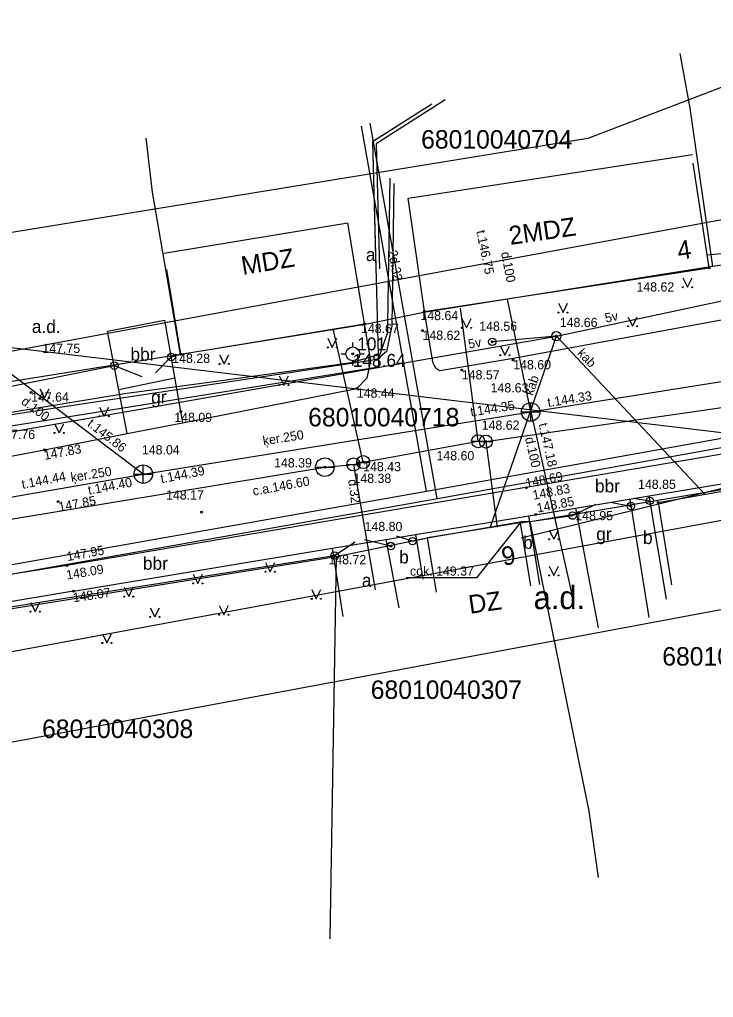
# Model space of a CAD drawing. Extents: x 728492 to 729038, y 272968 to 273171.
# Drawn here: x 728588.9 to 728626.4, y 273032.9 to 273085.8 of the extents above; entities that cross this region are included whole.
import ezdxf

# ---------------------------------------------------------------- set-up
doc = ezdxf.new("R2010")
doc.units = 0
for name, color, linetype in [('APGR_SARK_####_####_#', 7, 'Continuous'), ('BUVE_BDET_####_####_#', 7, 'Continuous'), ('BUVE_BDET_####_TKST_#', 7, 'Continuous'), ('BUVE_EKAS_####_####_#', 7, 'Continuous'), ('BUVE_EKAS_ADRS_TKST_#', 7, 'Continuous'), ('BUVE_EKAS_RAKS_TKST_#', 7, 'Continuous'), ('CELI_CAPM_####_####_#', 7, 'Continuous'), ('CELI_CMAL_####_####_#', 7, 'Continuous'), ('CELI_CSEG_####_TKST_#', 7, 'Continuous'), ('CELI_SEGL_####_####_#', 7, 'Continuous'), ('ELEK_ELEM_####_####_#', 7, 'Continuous'), ('ELEK_STUT_####_####_#', 7, 'Continuous'), ('ELEK_VADP_VSPR_####_#', 7, 'Continuous'), ('ELEK_VADP_ZSPR_####_#', 7, 'Continuous'), ('ELEK_VADV_ZSPR_####_#', 7, 'Continuous'), ('ELEK_VADV_ZSPR_TKST_#', 7, 'Continuous'), ('GEOD_ELEM_####_####_#', 7, 'Continuous'), ('GEOD_ELEM_####_TKST_#', 7, 'Continuous'), ('Level 62', 7, 'Continuous'), ('NORB_ELEM_####_####_#', 7, 'Continuous'), ('NORB_ZOGS_BARJ_####_#', 7, 'Continuous'), ('NORB_ZOGS_KOKA_####_#', 7, 'Continuous'), ('NORB_ZOGS_ZSTP_####_#', 7, 'Continuous'), ('RAMI_UZMR_####_####_#', 7, 'Continuous'), ('RELJ_AATZ_####_TKST_#', 7, 'Continuous'), ('RELJ_ELEM_####_####_#', 7, 'Continuous'), ('ROBZ_KADS_####_TKST_#', 7, 'Continuous'), ('ROBZ_UZMR_####_####_#', 7, 'Continuous'), ('SAKT_VADV_KLIN_####_#', 7, 'Continuous'), ('SILT_VADP_UDEN_####_#', 7, 'Continuous'), ('SILT_VADP_UDEN_TKST_#', 7, 'Continuous'), ('SKAN_ELEM_####_####_#', 7, 'Continuous'), ('SKAN_VADP_PAST_####_#', 7, 'Continuous'), ('SKAN_VADP_PAST_TKST_#', 7, 'Continuous'), ('TERT_ELEM_####_####_#', 7, 'Continuous'), ('TERT_IZMT_####_TKST_#', 7, 'Continuous'), ('UDTK_ELEM_####_####_#', 7, 'Continuous'), ('UDTK_ELEM_####_TKST_#', 7, 'Continuous'), ('UDTK_VADP_UDEN_####_#', 7, 'Continuous'), ('UDTK_VADP_UDEN_TKST_#', 7, 'Continuous')]:
    doc.layers.add(name, color=color, linetype=linetype)

msp = doc.modelspace()

# ---------------------------------------------------------------- linework, layer by layer
at = {"layer": 'APGR_SARK_####_####_#'}
for points in [[(728659.143, 273080.982), (728541.407, 273059.185)], [(728661.295, 273065.109), (728551.197, 273044.726)]]:
    msp.add_lwpolyline(points, dxfattribs=at)
at = {"layer": 'BUVE_BDET_####_####_#'}
msp.add_lwpolyline([(728615.971, 273058.601), (728613.605, 273055.621), (728609.798, 273055.621)], dxfattribs=at)
at = {"layer": 'BUVE_EKAS_####_####_#'}
for p, q in [((728609.897, 273076.179), (728625.296, 273078.536)), ((728626.186, 273072.407), (728625.319, 273078.071)), ((728610.787, 273070.05), (728609.897, 273076.179)), ((728596.708, 273073.202), (728606.645, 273074.845)), ((728607.549, 273069.376), (728606.645, 273074.845)), ((728597.612, 273067.733), (728596.855, 273072.309)), ((728610.787, 273070.05), (728626.186, 273072.407)), ((728597.612, 273067.733), (728607.549, 273069.376)), ((728623.429, 273059.709), (728632.791, 273061.372)), ((728623.429, 273059.709), (728624.16, 273055.247)), ((728615.971, 273058.601), (728610.946, 273057.793)), ((728615.971, 273058.601), (728616.519, 273055.191)), ((728611.429, 273054.849), (728610.946, 273057.793))]:
    msp.add_line(p, q, dxfattribs=at)
at = {"layer": 'CELI_CAPM_####_####_#'}
msp.add_line((728630.786, 273062.984), (728591.431, 273056.294), dxfattribs=at)
msp.add_lwpolyline([(728591.431, 273056.294), (728577.849, 273054.135), (728577.526, 273054.029), (728577.203, 273053.778), (728577.017, 273053.345), (728577.072, 273052.432)], dxfattribs=at)
at = {"layer": 'CELI_CMAL_####_####_#'}
for p, q in [((728611.241, 273067.302), (728610.787, 273070.05)), ((728615.604, 273067.516), (728631.326, 273070.412)), ((728607.884, 273067.35), (728607.549, 273069.376)), ((728611.627, 273066.852), (728615.604, 273067.516)), ((728597.702, 273064.026), (728607.125, 273065.877)), ((728590.22, 273062.556), (728594.693, 273063.435)), ((728622.936, 273060.066), (728641.923, 273063.209)), ((728588.309, 273062.194), (728590.22, 273062.556)), ((728590.22, 273062.556), (728590.22, 273062.556)), ((728623.877, 273054.483), (728622.936, 273060.066)), ((728610.303, 273057.974), (728618.954, 273059.406)), ((728618.954, 273059.406), (728620.178, 273052.925)), ((728616.415, 273058.986), (728617.013, 273055.27)), ((728610.303, 273057.974), (728610.692, 273055.554)), ((728591.788, 273054.908), (728605.801, 273057.228)), ((728605.801, 273057.228), (728606.37, 273053.532)), ((728608.701, 273057.708), (728608.701, 273057.708))]:
    msp.add_line(p, q, dxfattribs=at)
for points in [[(728594.693, 273063.435), (728593.642, 273068.981), (728596.728, 273069.566), (728597.702, 273064.026)], [(728607.125, 273065.877), (728607.688, 273066.453), (728607.884, 273067.35)], [(728591.788, 273054.908), (728577.072, 273052.432)]]:
    msp.add_lwpolyline(points, dxfattribs=at)
msp.add_arc((728611.826, 273067.413), 0.595, 190.7196, 250.457, dxfattribs=at)
at = {"layer": 'CELI_SEGL_####_####_#'}
for p, q in [((728594.693, 273063.435), (728597.702, 273064.026)), ((728618.954, 273059.406), (728622.936, 273060.066)), ((728621.895, 273059.893), (728622.932, 273053.483)), ((728608.701, 273057.708), (728610.303, 273057.974)), ((728605.801, 273057.228), (728608.701, 273057.708)), ((728608.701, 273057.708), (728609.398, 273053.999))]:
    msp.add_line(p, q, dxfattribs=at)
msp.add_lwpolyline([(728594.241, 273065.818), (728597.276, 273066.448)], dxfattribs=at)
at = {"layer": 'ELEK_ELEM_####_####_#'}
for centre, radius in [((728617.923, 273068.708), 0.25), ((728614.457, 273068.405), 0.2)]:
    msp.add_circle(centre, radius, dxfattribs=at)
at = {"layer": 'ELEK_STUT_####_####_#'}
msp.add_line((728617.923, 273068.708), (728614.457, 273068.405), dxfattribs=at)
at = {"layer": 'ELEK_VADP_VSPR_####_#'}
for points in [[(728611.184, 273081.264), (728607.971, 273079.223), (728608.156, 273072.311)], [(728609.286, 273080.058), (728607.971, 273079.223), (728608.297, 273067.03), (728567.061, 273060.412)]]:
    msp.add_lwpolyline(points, dxfattribs=at)
at = {"layer": 'ELEK_VADP_ZSPR_####_#'}
for points in [[(728611.913, 273081.49), (728608.174, 273079.115), (728608.355, 273072.352)], [(728537.081, 273033.933), (728536.029, 273037.608), (728532.423, 273051.927), (728532.247, 273053.87), (728532.195, 273055.313), (728532.733, 273055.949), (728533.306, 273056.402), (728544.74, 273057.861), (728548.075, 273058.286), (728556.859, 273059.593), (728568.226, 273061.284), (728585.454, 273064.109), (728594.552, 273065.598), (728599.536, 273066.281), (728606.829, 273067.282), (728608.394, 273067.733), (728608.806, 273068.923), (728608.813, 273069.373), (728608.935, 273077.264)], [(728609.132, 273076.972), (728609.028, 273069.268), (728608.736, 273067.883), (728608.238, 273067.455), (728607.796, 273067.368), (728594.151, 273065.314), (728588.415, 273064.454), (728582.59, 273063.515), (728568.697, 273061.216), (728567.895, 273060.73), (728567.578, 273060.071)]]:
    msp.add_lwpolyline(points, dxfattribs=at)
at = {"layer": 'ELEK_VADV_ZSPR_####_#'}
for p, q in [((728617.923, 273068.708), (728666.081, 273078.979)), ((728577.706, 273061.659), (728617.923, 273068.708)), ((728614.336, 273058.338), (728617.923, 273068.708)), ((728617.923, 273068.708), (728625.963, 273060.159))]:
    msp.add_line(p, q, dxfattribs=at)
at = {"layer": 'GEOD_ELEM_####_####_#'}
for p, q in [((728606.906, 273068.123), (728606.906, 273068.373)), ((728606.281, 273067.748), (728606.531, 273067.748)), ((728606.906, 273067.123), (728606.906, 273067.373)), ((728607.281, 273067.748), (728607.531, 273067.748))]:
    msp.add_line(p, q, dxfattribs=at)
for radius in [0.375, 0.05]:
    msp.add_circle((728606.906, 273067.748), radius, dxfattribs=at)
at = {"layer": 'NORB_ELEM_####_####_#'}
for centre in [(728594.005, 273067.114), (728597.087, 273067.582), (728622.982, 273059.794), (728621.956, 273059.514), (728618.801, 273058.999), (728610.139, 273057.615), (728608.966, 273057.347), (728605.924, 273056.836)]:
    msp.add_circle(centre, 0.202, dxfattribs=at)
at = {"layer": 'NORB_ZOGS_BARJ_####_#'}
for points in [[(728596.239, 273066.725), (728597.087, 273067.582)], [(728594.005, 273067.114), (728595.485, 273066.533)], [(728622.105, 273059.935), (728622.982, 273059.794)], [(728618.801, 273058.999), (728620.053, 273059.625)], [(728620.855, 273059.716), (728621.956, 273059.514)], [(728610.138, 273057.615), (728609.269, 273057.889)], [(728605.924, 273056.836), (728607.039, 273057.586)], [(728608.966, 273057.347), (728607.542, 273057.687)]]:
    msp.add_lwpolyline(points, dxfattribs=at)
at = {"layer": 'NORB_ZOGS_KOKA_####_#'}
msp.add_lwpolyline([(728626.077, 273073.117), (728630.292, 273073.503)], dxfattribs=at)
at = {"layer": 'NORB_ZOGS_ZSTP_####_#'}
for points in [[(728597.087, 273067.582), (728597.612, 273067.733)], [(728587.68, 273065.855), (728594.005, 273067.114)], [(728615.971, 273058.601), (728618.801, 273058.999)], [(728610.139, 273057.615), (728610.946, 273057.793)], [(728584.143, 273053.398), (728605.924, 273056.836)]]:
    msp.add_lwpolyline(points, dxfattribs=at)
at = {"layer": 'RAMI_UZMR_####_####_#'}
for points in [[(728726.814, 273102.175), (728686.914, 273096.216), (728659.323, 273094.615), (728619.629, 273079.414), (728545.121, 273067.256)], [(728545.121, 273067.256), (728525.538, 273066.106), (728511.145, 273059.016), (728527.731, 273033.328), (728550.271, 273033.197), (728572.013, 273034.886), (728580.562, 273045.27), (728653.673, 273058.931), (728671.713, 273053.291), (728688.721, 273058.407), (728702.149, 273066.922)]]:
    msp.add_lwpolyline(points, dxfattribs=at)
at = {"layer": 'RELJ_ELEM_####_####_#'}
for centre in [(728626.186, 273072.407), (728610.787, 273070.05), (728607.549, 273069.376), (728610.681, 273069.009), (728607.729, 273068.302), (728614.457, 273068.405), (728617.923, 273068.708), (728606.906, 273067.748), (728597.612, 273067.733), (728615.59, 273067.417), (728594.005, 273067.114), (728612.809, 273066.868), (728589.501, 273065.663), (728607.125, 273065.877), (728597.612, 273064.627), (728616.534, 273064.605), (728614.11, 273063.005), (728590.22, 273062.556), (728605.396, 273061.619), (728607.469, 273061.897), (728595.572, 273061.244), (728616.299, 273060.508), (728590.963, 273059.755), (728621.956, 273059.514), (728623.429, 273059.709), (728598.719, 273059.188), (728616.814, 273059.063), (728608.966, 273057.347), (728605.924, 273056.836), (728591.431, 273056.294), (728591.788, 273054.908)]:
    msp.add_circle(centre, 0.05, dxfattribs=at)
at = {"layer": 'ROBZ_UZMR_####_####_#'}
for p, q in [((728624.61, 273084.002), (728625.148, 273081.05)), ((728625.148, 273081.05), (728626.365, 273072.477)), ((728596.07, 273076.503), (728595.736, 273079.424)), ((728597.584, 273067.721), (728596.07, 273076.503)), ((728630.305, 273073.064), (728626.365, 273072.477)), ((728626.365, 273072.477), (728610.761, 273069.994)), ((728610.761, 273069.994), (728607.569, 273069.334)), ((728607.569, 273069.334), (728597.584, 273067.721)), ((728597.584, 273067.721), (728547.311, 273059.662)), ((728616.498, 273058.682), (728633.894, 273061.592)), ((728610.841, 273057.776), (728616.062, 273058.672)), ((728616.062, 273058.672), (728616.498, 273058.682)), ((728619.697, 273042.998), (728616.498, 273058.682)), ((728606.005, 273056.779), (728610.841, 273057.776)), ((728578.327, 273052.35), (728606.005, 273056.779)), ((728606.005, 273056.779), (728605.672, 273036.097)), ((728620.2, 273039.418), (728619.697, 273042.998))]:
    msp.add_line(p, q, dxfattribs=at)
at = {"layer": 'SAKT_VADV_KLIN_####_#'}
msp.add_line((728578.857, 273069.237), (728635.134, 273062.502), dxfattribs=at)
msp.add_lwpolyline([(728635.134, 273062.502), (728616.023, 273057.783)], dxfattribs=at)
at = {"layer": 'SILT_VADP_UDEN_####_#'}
for p, q in [((728610.89, 273060.328), (728607.371, 273080.08)), ((728611.47, 273059.924), (728607.852, 273080.229))]:
    msp.add_line(p, q, dxfattribs=at)
for points in [[(728554.662, 273032.952), (728554.113, 273035.473), (728554.267, 273035.774), (728581.419, 273054.878), (728582.018, 273055.208), (728610.89, 273060.328), (728630.183, 273063.782), (728638.039, 273065.289), (728652.893, 273068.386), (728653.925, 273076.859), (728654.802, 273077.089)], [(728555.193, 273032.922), (728554.64, 273035.405), (728554.656, 273035.436), (728581.684, 273054.453), (728582.187, 273054.73), (728610.978, 273059.835), (728630.274, 273063.29), (728638.144, 273064.8), (728653.493, 273067.873), (728654.384, 273076.462), (728654.897, 273076.597)]]:
    msp.add_lwpolyline(points, dxfattribs=at)
at = {"layer": 'SKAN_ELEM_####_####_#'}
for p, q in [((728616.534, 273064.105), (728616.534, 273065.105)), ((728616.034, 273064.605), (728617.034, 273064.605)), ((728595.572, 273060.744), (728595.572, 273061.744)), ((728595.072, 273061.244), (728596.072, 273061.244))]:
    msp.add_line(p, q, dxfattribs=at)
for centre in [(728616.534, 273064.605), (728595.572, 273061.244)]:
    msp.add_circle(centre, 0.5, dxfattribs=at)
at = {"layer": 'SKAN_VADP_PAST_####_#'}
for points in [[(728616.534, 273064.605), (728669.124, 273072.987)], [(728616.534, 273064.605), (728615.275, 273070.702)], [(728565.936, 273055.685), (728588.276, 273059.976), (728595.572, 273061.244), (728588.275, 273066.761)], [(728595.572, 273061.244), (728616.534, 273064.605), (728618.819, 273054.491)]]:
    msp.add_lwpolyline(points, dxfattribs=at)
at = {"layer": 'TERT_ELEM_####_####_#'}
for p, q in [((728624.768, 273071.859), (728625.018, 273071.359)), ((728625.018, 273071.359), (728625.268, 273071.859)), ((728618.033, 273070.488), (728618.283, 273069.988)), ((728618.283, 273069.988), (728618.533, 273070.488)), ((728612.81, 273069.66), (728613.06, 273069.16)), ((728613.06, 273069.16), (728613.31, 273069.66)), ((728621.8, 273069.745), (728622.05, 273069.245)), ((728622.05, 273069.245), (728622.3, 273069.745)), ((728605.551, 273068.597), (728605.801, 273068.097)), ((728605.801, 273068.097), (728606.051, 273068.597)), ((728614.893, 273068.174), (728615.143, 273067.674)), ((728615.143, 273067.674), (728615.393, 273068.174)), ((728599.701, 273067.703), (728599.951, 273067.203)), ((728599.951, 273067.203), (728600.201, 273067.703)), ((728602.924, 273066.562), (728603.174, 273066.062)), ((728603.174, 273066.062), (728603.424, 273066.562)), ((728589.983, 273065.867), (728590.233, 273065.367)), ((728590.233, 273065.367), (728590.483, 273065.867)), ((728593.206, 273064.874), (728593.456, 273064.374)), ((728593.456, 273064.374), (728593.706, 273064.874)), ((728590.768, 273063.969), (728591.018, 273063.469)), ((728591.018, 273063.469), (728591.268, 273063.969)), ((728617.535, 273058.217), (728617.785, 273057.717)), ((728617.785, 273057.717), (728618.035, 273058.217)), ((728602.183, 273056.461), (728602.433, 273055.961)), ((728602.433, 273055.961), (728602.683, 273056.461)), ((728617.535, 273056.26), (728617.785, 273055.76)), ((728617.785, 273055.76), (728618.035, 273056.26)), ((728598.273, 273055.828), (728598.523, 273055.328)), ((728598.523, 273055.328), (728598.773, 273055.828)), ((728594.533, 273055.117), (728594.783, 273054.617)), ((728594.783, 273054.617), (728595.033, 273055.117)), ((728604.684, 273054.994), (728604.934, 273054.494)), ((728604.934, 273054.494), (728605.184, 273054.994)), ((728589.475, 273054.303), (728589.725, 273053.803)), ((728589.725, 273053.803), (728589.975, 273054.303)), ((728599.682, 273054.13), (728599.932, 273053.63)), ((728599.932, 273053.63), (728600.182, 273054.13)), ((728595.944, 273054.015), (728596.194, 273053.515)), ((728596.194, 273053.515), (728596.444, 273054.015)), ((728593.357, 273052.605), (728593.607, 273052.105)), ((728593.607, 273052.105), (728593.857, 273052.605))]:
    msp.add_line(p, q, dxfattribs=at)
for centre, radius in [((728624.768, 273071.359), 0.028), ((728625.268, 273071.359), 0.0263), ((728618.032, 273069.988), 0.028), ((728618.532, 273069.988), 0.0263), ((728612.81, 273069.159), 0.028), ((728613.31, 273069.159), 0.0263), ((728621.8, 273069.245), 0.028), ((728622.3, 273069.245), 0.0263), ((728605.551, 273068.096), 0.028), ((728606.051, 273068.096), 0.0263), ((728614.893, 273067.673), 0.028), ((728615.393, 273067.673), 0.0263), ((728599.701, 273067.203), 0.028), ((728600.201, 273067.203), 0.0263), ((728602.923, 273066.061), 0.028), ((728603.423, 273066.061), 0.0263), ((728589.983, 273065.366), 0.028), ((728590.483, 273065.366), 0.0263), ((728593.205, 273064.374), 0.028), ((728593.705, 273064.374), 0.0263), ((728590.768, 273063.469), 0.028), ((728591.268, 273063.469), 0.0263), ((728617.535, 273057.717), 0.028), ((728618.035, 273057.717), 0.0263), ((728602.183, 273055.961), 0.028), ((728602.683, 273055.961), 0.0263), ((728617.535, 273055.759), 0.028), ((728618.035, 273055.759), 0.0263), ((728598.273, 273055.328), 0.028), ((728598.773, 273055.328), 0.0263), ((728594.533, 273054.617), 0.028), ((728595.033, 273054.617), 0.0263), ((728604.684, 273054.493), 0.028), ((728605.184, 273054.493), 0.0263), ((728589.475, 273053.802), 0.028), ((728589.975, 273053.802), 0.0263), ((728595.944, 273053.515), 0.028), ((728596.444, 273053.515), 0.0263), ((728599.681, 273053.63), 0.028), ((728600.181, 273053.63), 0.0263), ((728593.356, 273052.104), 0.028), ((728593.856, 273052.104), 0.0263)]:
    msp.add_circle(centre, radius, dxfattribs=at)
at = {"layer": 'UDTK_ELEM_####_####_#'}
for p, q in [((728613.337, 273063.022), (728614.039, 273063.022)), ((728613.759, 273063.005), (728614.461, 273063.005)), ((728604.897, 273061.619), (728605.897, 273061.619)), ((728606.594, 273061.767), (728607.296, 273061.767)), ((728607.118, 273061.897), (728607.82, 273061.897))]:
    msp.add_line(p, q, dxfattribs=at)
for centre, radius in [((728613.688, 273063.022), 0.351), ((728614.11, 273063.005), 0.351), ((728605.397, 273061.619), 0.5), ((728606.945, 273061.767), 0.351), ((728607.469, 273061.897), 0.351)]:
    msp.add_circle(centre, radius, dxfattribs=at)
at = {"layer": 'UDTK_VADP_UDEN_####_#'}
for points in [[(728613.688, 273063.022), (728612.733, 273070.229)], [(728536.753, 273051.73), (728562.041, 273055.954), (728585.763, 273058.374), (728605.397, 273061.619), (728606.945, 273061.767), (728607.469, 273061.897), (728613.688, 273063.022), (728614.11, 273063.005), (728657.437, 273069.243)], [(728607.469, 273061.897), (728605.863, 273069.033)], [(728614.11, 273063.005), (728614.723, 273058.38)], [(728606.945, 273061.767), (728608.123, 273054.985)]]:
    msp.add_lwpolyline(points, dxfattribs=at)

# ---------------------------------------------------------------- texts
at = {"layer": 'BUVE_BDET_####_TKST_#'}
msp.add_text('cok. 149.37', height=0.49999, dxfattribs=at).set_placement((728610.003, 273055.747))
at = {"layer": 'BUVE_EKAS_ADRS_TKST_#'}
for s, rotation, p in [('4', 8.702, (728624.543, 273072.834)), ('9', 9.738, (728615.048, 273056.28))]:
    msp.add_text(s, height=1, rotation=rotation, dxfattribs=at).set_placement(p)
at = {"layer": 'BUVE_EKAS_RAKS_TKST_#'}
for s, rotation, p in [('2MDZ', 8.259, (728615.432, 273073.645)), ('MDZ', 9.388, (728600.958, 273072.016)), ('DZ', 8.101, (728613.246, 273053.681))]:
    msp.add_text(s, height=1, rotation=rotation, dxfattribs=at).set_placement(p)
at = {"layer": 'CELI_CSEG_####_TKST_#'}
for s, p in [('a', (728607.614, 273072.775)), ('bbr', (728594.878, 273067.378)), ('gr', (728595.996, 273065.066)), ('bbr', (728620.012, 273060.253)), ('b', (728616.123, 273057.193)), ('gr', (728620.081, 273057.657)), ('b', (728622.611, 273057.458)), ('bbr', (728595.55, 273056.065)), ('b', (728609.42, 273056.406)), ('a', (728607.397, 273055.146))]:
    msp.add_text(s, height=0.7, dxfattribs=at).set_placement(p)
at = {"layer": 'ELEK_VADV_ZSPR_TKST_#'}
for s, rotation, p in [('5v', 12.0395, (728620.608, 273069.434)), ('5v', 9.9415, (728613.199, 273068.032)), ('kab', 313.2425, (728619.026, 273067.754)), ('kab', 70.9194, (728616.642, 273065.464))]:
    msp.add_text(s, height=0.5, rotation=rotation, dxfattribs=at).set_placement(p)
at = {"layer": 'GEOD_ELEM_####_TKST_#'}
for s, p in [('101', (728607.147, 273067.938)), ('148.64', (728606.906, 273067.048))]:
    msp.add_text(s, height=0.7, dxfattribs=at).set_placement(p)
at = {"layer": 'Level 62'}
msp.add_text('a.d.', height=1.25, dxfattribs=at).set_placement((728616.692, 273053.936))
at = {"layer": 'RELJ_AATZ_####_TKST_#'}
for s, p in [(' 148.62', (728622.071, 273071.125)), (' 148.64', (728610.38, 273069.575)), (' 148.67', (728607.167, 273068.876)), (' 148.56', (728613.567, 273068.998)), (' 148.66', (728617.921, 273069.201)), ('148.62', (728610.681, 273068.509)), (' 147.75', (728589.927, 273067.796)), (' 148.28', (728596.952, 273067.258)), ('148.60', (728615.59, 273066.917)), ('148.57', (728612.809, 273066.368)), ('148.44', (728607.125, 273065.377)), ('147.64', (728589.501, 273065.163)), (' 148.09', (728597.065, 273064.062)), ('147.76', (728587.672, 273063.14)), (' 148.85', (728622.158, 273060.443)), (' 148.17', (728596.619, 273059.863)), (' 148.95', (728618.762, 273058.75)), (' 148.80', (728607.361, 273058.158)), (' 148.72', (728605.403, 273056.366))]:
    msp.add_text(s, height=0.5, dxfattribs=at).set_placement(p)
for s, rotation, p in [('147.83', 10.6625, (728590.241, 273062.007)), ('148.69', 11.319, (728616.305, 273060.498)), ('148.83', 10.9383, (728616.689, 273059.851)), ('147.85', 10.5336, (728591.034, 273059.211)), ('148.85', 10.9383, (728616.912, 273059.156)), ('147.95', 10.2697, (728591.479, 273056.532)), ('148.09', 9.5409, (728591.444, 273055.53)), ('148.07', 8.2992, (728591.805, 273054.307))]:
    msp.add_text(s, height=0.5, rotation=rotation, dxfattribs=at).set_placement(p)
at = {"layer": 'ROBZ_KADS_####_TKST_#'}
for s, p in [('68010040704', (728610.605, 273078.859)), ('68010040718', (728604.494, 273063.825)), ('68010040306', (728623.653, 273050.881)), ('68010040307', (728607.879, 273049.078)), ('68010040308', (728590.095, 273046.962))]:
    msp.add_text(s, height=1, dxfattribs=at).set_placement(p)
at = {"layer": 'SILT_VADP_UDEN_TKST_#'}
msp.add_text('2d.32', height=0.5, rotation=280.101, dxfattribs=at).set_placement((728608.821, 273073.32))
at = {"layer": 'SKAN_ELEM_####_####_#'}
for s, p in [('148.63', (728614.365, 273065.664)), ('148.04', (728595.497, 273062.308))]:
    msp.add_text(s, height=0.5, dxfattribs=at).set_placement(p)
at = {"layer": 'SKAN_VADP_PAST_TKST_#'}
for s, rotation, p in [('t.146.75', 281.669, (728613.586, 273074.385)), ('d.100', 280.97, (728614.926, 273073.223)), ('t.144.33', 9.141, (728617.486, 273064.871)), ('d.100', 322.907, (728588.923, 273065.087)), ('t.144.35', 9.141, (728613.312, 273064.356)), ('t.145.86', 322.073, (728592.505, 273063.882)), ('ķer.250', 9.109, (728602.081, 273062.793)), ('t.147.18', 282.782, (728616.952, 273063.948)), ('d.100', 282.782, (728616.225, 273063.191)), ('ķer.250', 9.109, (728591.687, 273060.813)), ('t.144.39', 10.873, (728596.554, 273060.747)), ('t.144.44', 10.873, (728589.041, 273060.442)), ('t.144.40', 10.873, (728592.628, 273060.12))]:
    msp.add_text(s, height=0.5, rotation=rotation, dxfattribs=at).set_placement(p)
at = {"layer": 'TERT_IZMT_####_TKST_#'}
msp.add_text('a.d.', height=0.7, dxfattribs=at).set_placement((728589.541, 273068.881))
at = {"layer": 'UDTK_ELEM_####_TKST_#'}
for s, p in [('148.62', (728613.882, 273063.644)), ('148.60', (728611.437, 273061.993)), ('148.39', (728602.649, 273061.604)), ('148.43', (728607.469, 273061.397)), ('148.38', (728606.945, 273060.764))]:
    msp.add_text(s, height=0.5, dxfattribs=at).set_placement(p)
at = {"layer": 'UDTK_VADP_UDEN_TKST_#'}
for s, rotation, p in [('c.a.146.60', 10.4148, (728601.536, 273060.075)), ('d.32', 277.4522, (728606.657, 273060.934))]:
    msp.add_text(s, height=0.5, rotation=rotation, dxfattribs=at).set_placement(p)

doc.saveas('drawing.dxf')
